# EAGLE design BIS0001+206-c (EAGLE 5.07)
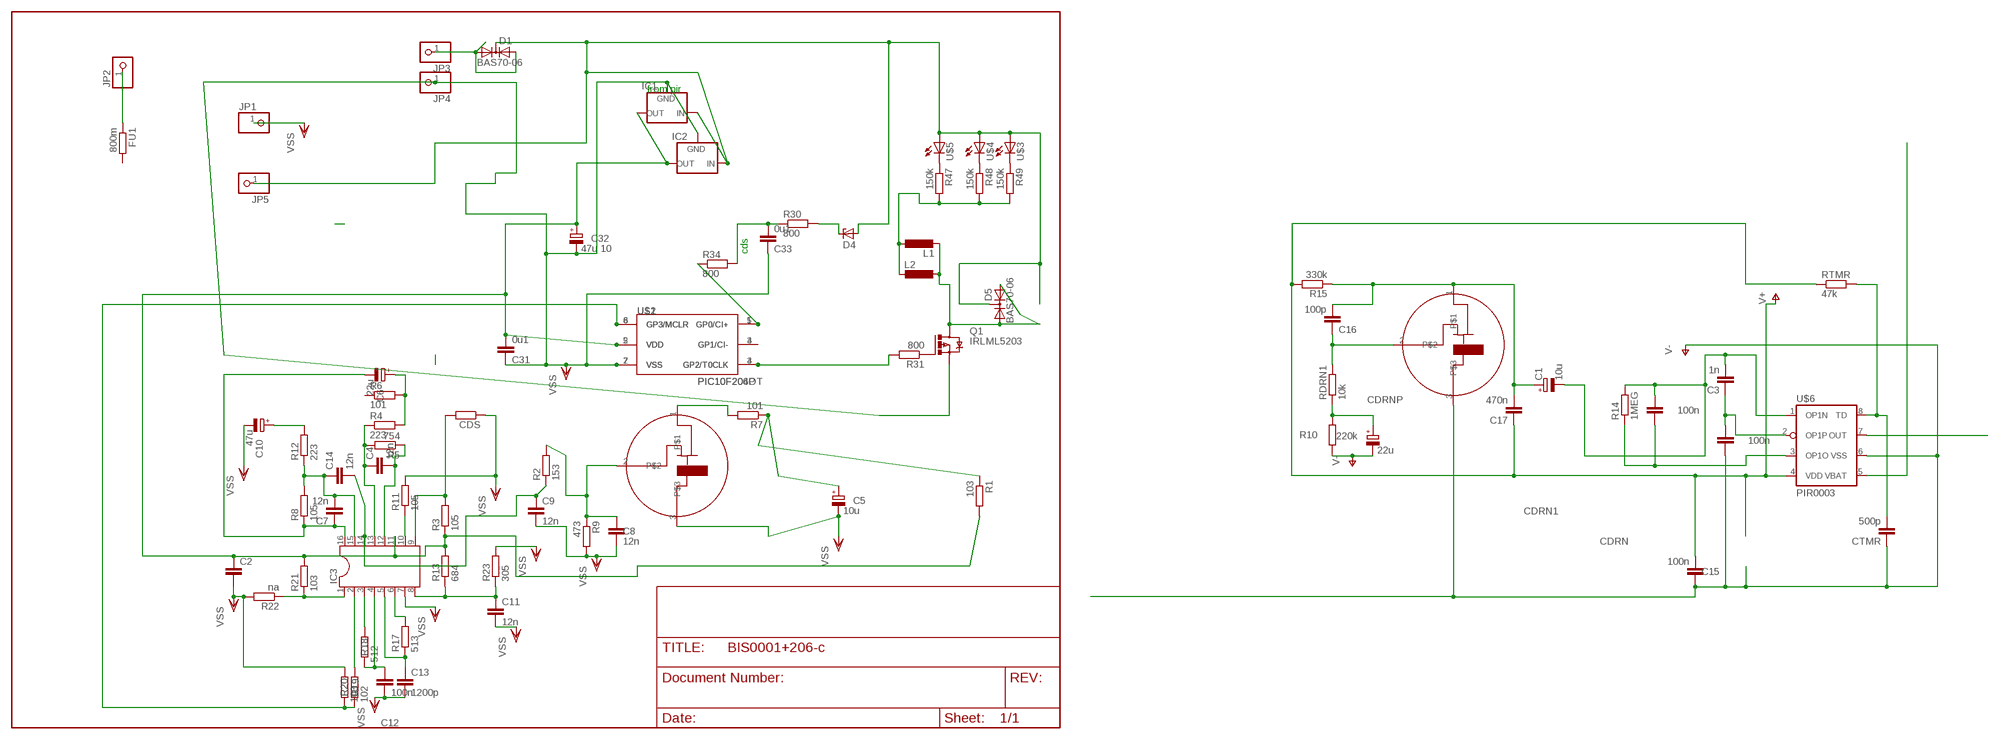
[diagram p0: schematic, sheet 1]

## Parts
C1  10u  CPOL-EUSMCA  [SMC_A]
C2  C-EUC0805  [C0805]
C3  1n  C-EUC0805  [C0805]
C4  12n  C-EUC0805  [C0805]
C5  10u  CPOL-EUE2.5-5  [E2,5-5]
C6  22u  CPOL-EUE2.5-5  [E2,5-5]
C7  12n  C-EUC0805  [C0805]
C8  12n  C-EUC0805  [C0805]
C9  12n  C-EUC0805  [C0805]
C10  47u  CPOL-EUE2.5-5  [E2,5-5]
C11  12n  C-EUC0805  [C0805]
C12  100n  C-EUC0805  [C0805]
C13  1200p  C-EUC0805  [C0805]
C14  12n  C-EUC0805  [C0805]
C15  100n  C-EUC1206  [C1206]
C16  100p  C-EUC0805  [C0805]
C17  470n  C-EUC0805  [C0805]
C31  0u1  C-EUC1206  [C1206]
C32  47u 10  CPOL-EUE2.5-5  [E2,5-5]
C33  0u1  C-EUC1206  [C1206]
CDRN  100n  C-EUC0805  [C0805]
CDRN1  100n  C-EUC0805  [C0805]
CDRNP  22u  CPOL-EUSMCB  [SMC_B]
CDS  R-EU_0207/5V  [0207/5V]
CTMR  500p  C-EUC0805  [C0805]
D1  BAS70-06  [SOT23]
D4  ZENER-DIODESOT23  [SOT23]
D5  BAS70-06  [SOT23]
FU1  800m  R-EU_0204/5  [0204/5]
IC1  XC63FPT  [TO92]
IC2  XC63FPP  [SOT89R]
IC3  DIL16SO16  [SO16]
JP1  PINHD-1X1  [1X01]
JP2  PINHD-1X1  [1X01]
JP3  PINHD-1X1  [1X01]
JP4  PINHD-1X1  [1X01]
JP5  PINHD-1X1  [1X01]
L1  L-EUL5650M  [L5650M]
L2  L-EU0207/7  [0207/7@1]
PIR  RE200B  [R200B]
PIR1  RE200B  [R200B]
Q1  IRLML5203  [MICRO3]
R1  103  R-EU_R0805  [R0805]
R2  153  R-EU_R0805  [R0805]
R3  105  R-EU_R0805  [R0805]
R4  223  R-EU_R0805  [R0805]
R5  754  R-EU_R0805  [R0805]
R6  101  R-EU_R0805  [R0805]
R7  101  R-EU_R0805  [R0805]
R8  105  R-EU_R0805  [R0805]
R9  473  R-EU_R0805  [R0805]
R10  220k  R-EU_R0805  [R0805]
R11  105  R-EU_R0805  [R0805]
R12  223  R-EU_R0805  [R0805]
R13  684  R-EU_R0805  [R0805]
R14  1MEG  R-EU_R0805  [R0805]
R15  330k  R-EU_R0805  [R0805]
R17  513  R-EU_R0805  [R0805]
R18  512  R-EU_R0805  [R0805]
R19  102  R-EU_R0805  [R0805]
R20  103  R-EU_R0805  [R0805]
R21  103  R-EU_R0805  [R0805]
R22  na  R-EU_R0805  [R0805]
R23  305  R-EU_R0805  [R0805]
R30  800  R-EU_R1206  [R1206]
R31  800  R-EU_R1206  [R1206]
R34  800  R-EU_R1206  [R1206]
R47  150k  R-EU_R1206  [R1206]
R48  150k  R-EU_R1206  [R1206]
R49  150k  R-EU_R1206  [R1206]
RDRN1  10k  R-EU_R0805  [R0805]
RTMR  47k  R-EU_R0805  [R0805]
U$1  PIC10F206P  [DIL8]
U$2  PIC10F204OT  [SOT23-6]
U$3  LED5MM  [LED5MM]
U$4  LED5MM  [LED5MM]
U$5  LED5MM  [LED5MM]
U$6  PIR0003  [SO08]

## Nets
GP3: U$6.7(OUT)
N$1: D1.1(A1) D1.2(A2) JP3.1
N$4: FU1.1 JP2.1
N$6: D4.3(C) R30.2
N$7: D1.3(C) D4.1(A) D5.3(C) IC1.2(IN) IC2.2(IN) JP5.1 U$3.A U$4.A U$5.A
N$8: C1.+ C16.2 C17.2 PIR1.1 R15.1
N$9: CDRNP.+ R10.2 RDRN1.1
N$10: Q1.1(G) R31.1
N$11: IC3.1 R21.1 R22.1
N$12: R19.1 R20.1 U$1.8(GP3/MCLR) U$2.6(GP3/MCLR)
N$13: U$1.4(GP1/CI-) U$2.3(GP1/CI-)
N$14: R31.2 U$1.3(GP2/T0CLK) U$2.4(GP2/T0CLK)
N$15: C1.- C3.2 CDRN1.2 R14.2 U$6.1(OP1N)
N$17: C33.2 R30.1 R34.2
N$18: C3.1 CDRN.2 U$6.2(OP1P)
N$20: CDRN1.1 R14.1 U$6.3(OP1O)
N$21: CTMR.2 RTMR.2 U$6.8(TD)
N$22: L1.1 L2.2 R47.2 R48.2 R49.2
N$23: C16.1 PIR1.2 RDRN1.2
N$24: IC3.2 R19.2
N$25: C12.1 IC3.4 R18.1
N$26: D5.1(A1) D5.2(A2) L1.2 L2.1 Q1.3(D)
N$27: IC3.3 R18.2
N$28: C11.1 IC3.8 R13.1 R23.1
N$29: R34.1 U$1.5(GP0/CI+) U$2.1(GP0/CI+)
N$30: C13.1 IC3.5 R17.1
N$31: IC3.6 R17.2
N$32: IC3.10 R11.1
N$34: C4.2 IC3.12 R5.1
N$35: C4.1 IC3.13 R4.1 R5.2
N$36: CDS.2 IC3.9 R3.2
N$37: C6.+ R4.2 R6.2
N$38: R47.1 U$5.K(C)
N$39: C9.1 C14.2 IC3.14 R2.1
N$40: C7.2 C14.1 IC3.15 R8.2 R12.1
N$41: C6.- C7.1 IC3.16 R8.1
N$42: PIR.1 R7.2
N$43: C5.+ R1.1 R7.1
N$44: C10.+ R12.2
N$46: C8.1 PIR.2 R2.2 R9.1
N$54: R48.1 U$4.K(C)
N$55: R49.1 U$3.K(C)
V2CC: C2.1 C31.2 C32.+ IC1.3(OUT) IC2.3(OUT) IC3.11 R1.2 R3.1 R13.2 R21.2 U$1.2(VDD) U$2.5(VDD)
V5: U$6.5(VBAT)
V+: C15.2 C17.1 R15.2 RTMR.1 U$6.4(VDD)
V-: C15.1 CDRN.1 CDRNP.- CTMR.1 PIR1.3 R10.1 U$6.6(VSS)
VSS: C2.2 C5.- C8.2 C9.2 C10.- C11.2 C12.2 C13.2 C31.1 C32.- C33.1 CDS.1 IC1.1(GND) IC2.1(GND) IC3.7 JP1.1 JP4.1 PIR.3 Q1.2(S) R9.2 R11.2 R20.2 R22.2 R23.2 U$1.7(VSS) U$2.2(VSS)
Unconnected: FU1.2 R6.1

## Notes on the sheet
- from pir
- cds

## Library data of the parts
C1 C5 C6 C10 C32 CDRNP = rcl:CPOL-EU: POLARIZED CAPACITOR, European symbol
C2 C4 C7-C9 C11-C14 = rcl-2:C-EU: CAPACITOR, European symbol
C3 C15-C17 C31 C33 CDRN CDRN1 CTMR = rcl:C-EU: CAPACITOR, European symbol
CDS = rcl(2):R-EU_: RESISTOR, European symbol
D1 D5 = diode-1:BAS70-06: Silicon Schottky Diodes General-purpose diode for high-speed switching
D4 = diode-1:ZENER-DIODE: Z-Diode
FU1 R10 R14 R15 R30 R31 R34 R47-R49 RDRN1 RTMR = rcl:R-EU_: RESISTOR, European symbol
IC1 IC2 = v-reg:XC63FP: Positiv Voltage Regulators www.torex.co.jp/english/product/pro02/pdf/0201_xc62fp.pdf
IC3 = ic-package:DIL16: Dual In Line / Socket
JP1-JP5 = pinhead:PINHD-1X1: PIN HEADER
L1 = rcl-2:L-EU: INDUCTOR, European symbol
L2 = rcl:L-EU: INDUCTOR, European symbol
PIR PIR1 = photo-elements:RE200B
Q1 = transistor-power:IRLML5203: HEXFET P-Channel Power MOSFET
R1-R9 R11-R13 R17-R23 = rcl-2:R-EU_: RESISTOR, European symbol
U$1 U$2 = microchip-3:PIC10F2*: uPC nW 0,25/0,5k Program Flash memory Comparator
U$3-U$5 = led(3):LED: LED
U$6 = linear:PIR0003

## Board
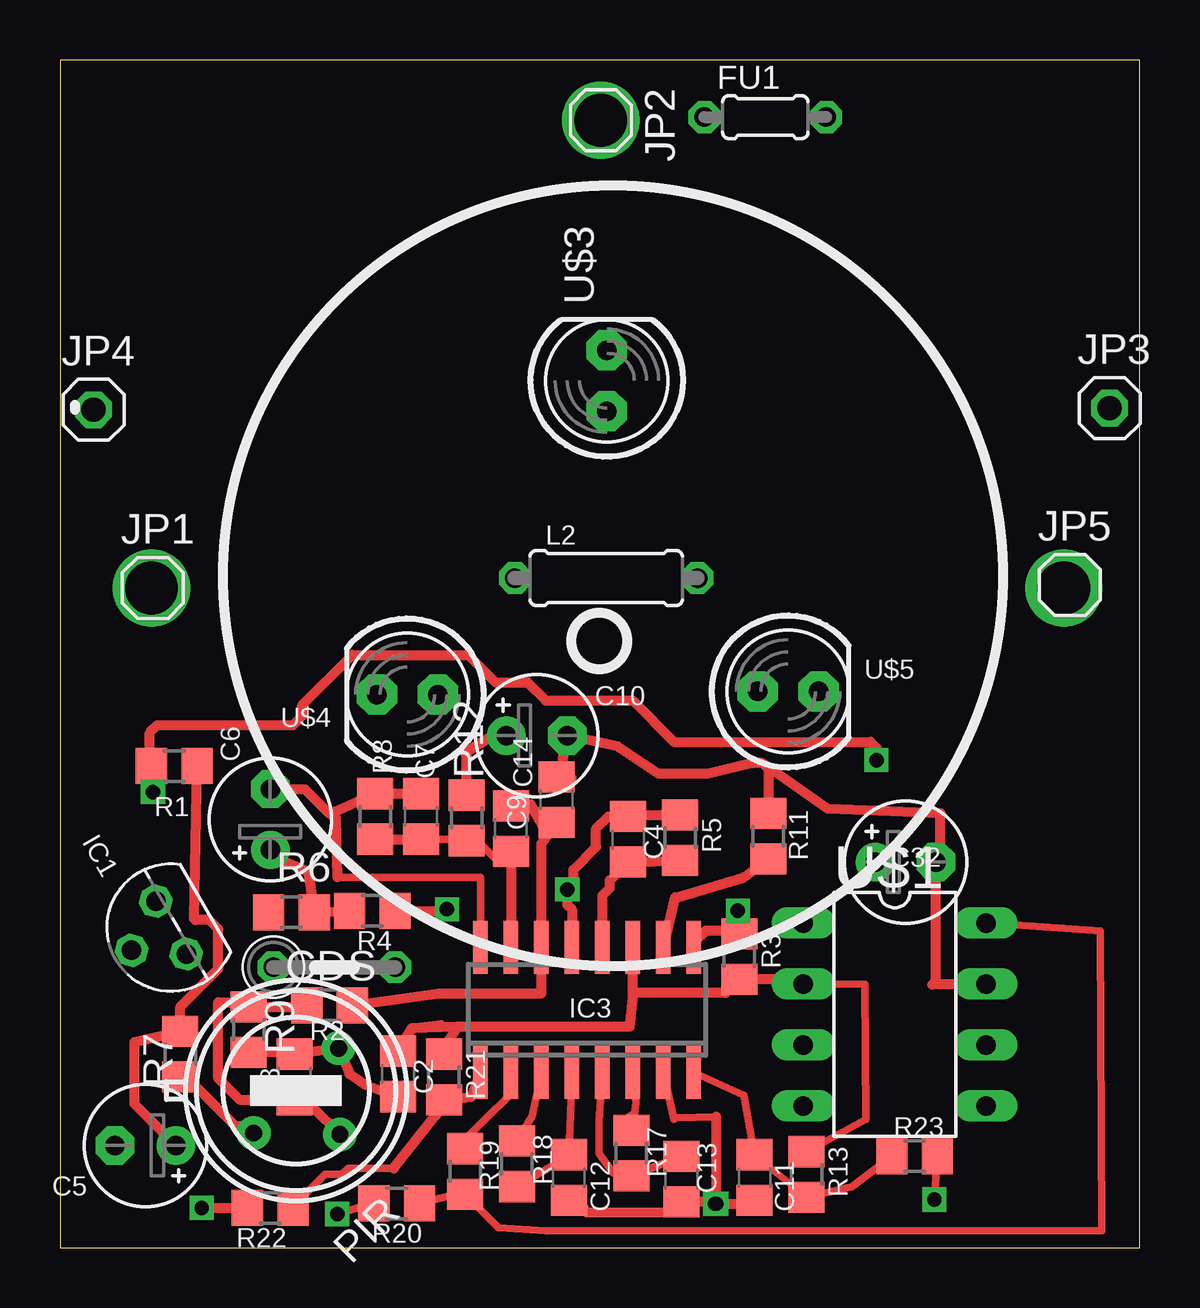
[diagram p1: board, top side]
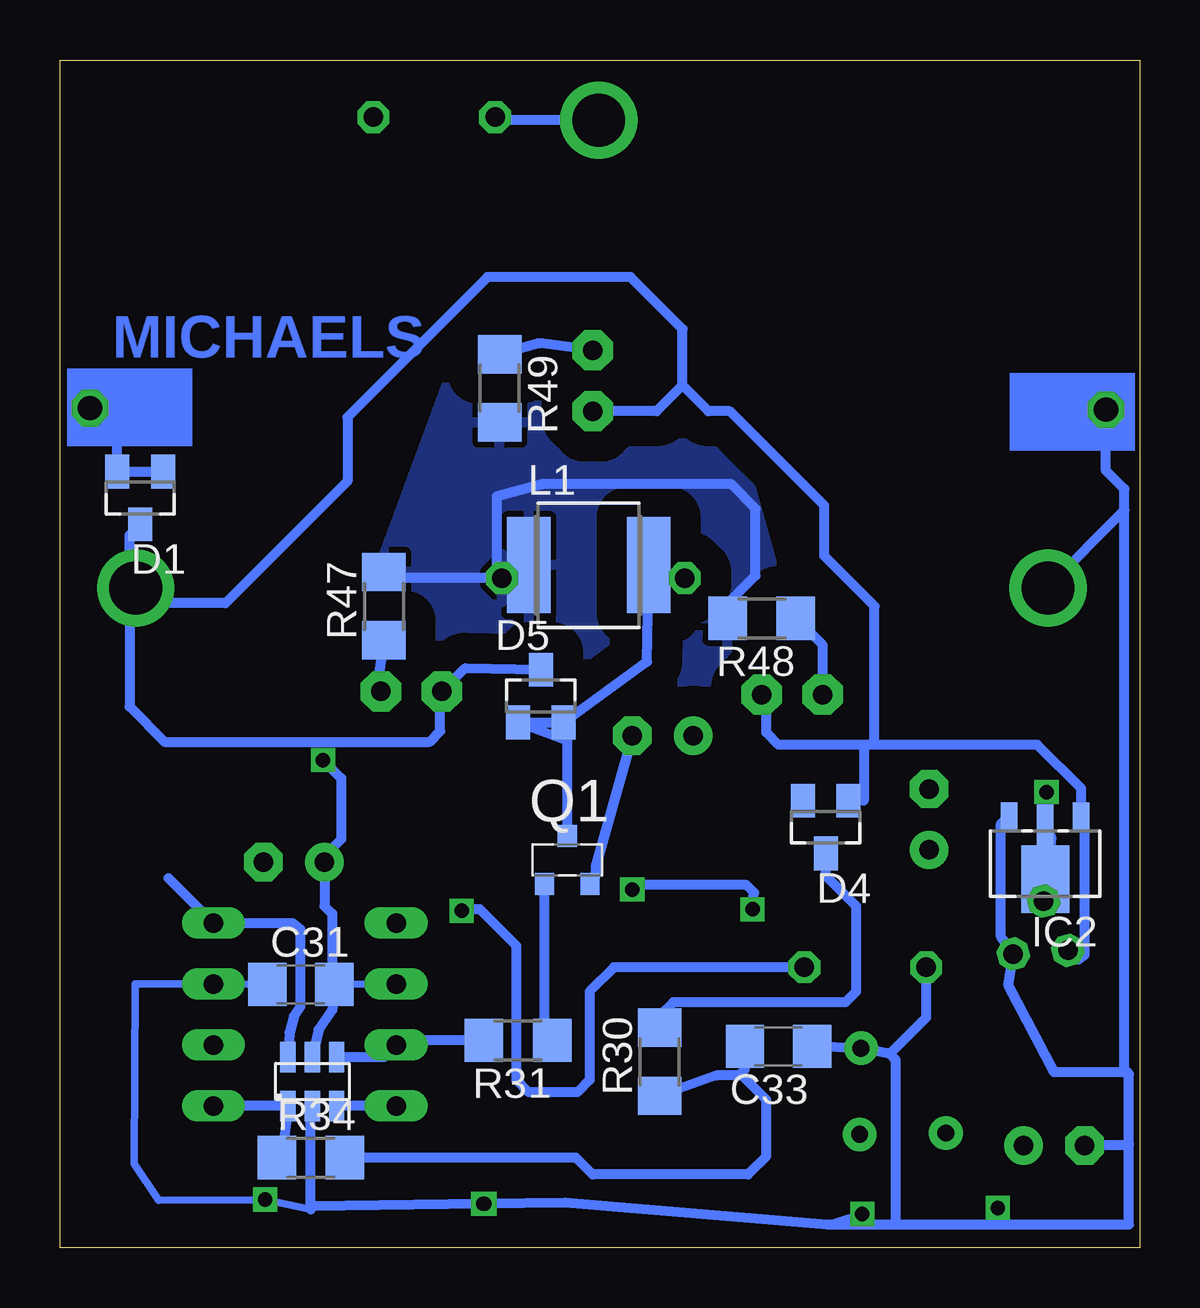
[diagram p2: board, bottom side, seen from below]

Size 45 x 49.5 mm. Coordinates in mm from the lower left corner, seen from the top.
Outline: 0,0 45,0 45,49.5 0,49.5 0,0
Copper layers (1*16): Top 0.035mm / dielectric 1.5mm / Bottom 0.035mm
Design rules "default": minimum track width 10mil, minimum drill 24mil, track to track 8mil, track to pad 8mil, pad to pad 8mil, via to via 8mil, smd to smd 8mil, copper to edge 40mil, drill to drill 8mil, minimum pad ring 10mil, minimum via ring 8mil, stop-mask expansion 4mil, vias tented up to drill 0mil, thermal gap 10mil

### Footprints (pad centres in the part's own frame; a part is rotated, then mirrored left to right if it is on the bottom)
SMC_A = smd 1.6 x 1.4: + -1.5,0; - 1.5,0
C0805 = smd 1.3 x 1.5: 1 -0.95,0; 2 0.95,0
E2,5-5 = drill 0.813 pad 1.6 round: + -1.27,0 | drill 0.813 pad 1.6 octagon: - 1.27,0
C1206 = smd 1.6 x 1.8: 1 -1.4,0; 2 1.4,0
SMC_B = smd 1.6 x 2.4: + -1.5,0; - 1.5,0
0207/5V = drill 0.813 octagon: 1 -2.54,0; 2 2.54,0
SOT23 = smd 1 x 1.4: 1 -0.95,-1.1; 2 0.95,-1.1; 3 0,1.1
0204/5 = drill 0.813 octagon: 1 -2.54,0; 2 2.54,0
TO92 = drill 0.813 octagon: 1 -1.27,0; 2 0,1.905; 3 1.27,0
SOT89R = smd 0.7 x 1.1: 1 1.5,-1.75; 2 -1.5,-1.75 | smd 0.7 x 1.8: 3 0,-1.4 | smd 2 x 2.8: 4 0,0.9
SO16 = smd 0.6 x 2.2: 1 -4.445,-2.6; 2 -3.175,-2.6; 3 -1.905,-2.6; 4 -0.635,-2.6; 5 0.635,-2.6; 6 1.905,-2.6; 7 3.175,-2.6; 8 4.445,-2.6; 9 4.445,2.6; 10 3.175,2.6; 11 1.905,2.6; 12 0.635,2.6; 13 -0.635,2.6; 14 -1.905,2.6; 15 -3.175,2.6; 16 -4.445,2.6
1X01 = drill 1.016 octagon: 1 0,0
L5650M = smd 1.8 x 4: 1 -2.5,0; 2 2.5,0
0207/7@1 = drill 0.813 octagon: 1 -3.81,0; 2 3.81,0
R200B = drill 0.7 pad 1.4 round: 1 -2.5,0; 2 0,-2.58; 3 2.5,0
MICRO3 = smd 0.8 x 0.9: 1 -0.95,-1; 2 0.95,-1; 3 0,1
R0805 = smd 1.3 x 1.5: 1 -0.95,0; 2 0.95,0
R1206 = smd 1.6 x 1.803: 1 -1.422,0; 2 1.422,0
DIL8 = drill 0.813 long: 1 -3.81,-3.81; 2 -1.27,-3.81; 3 1.27,-3.81; 4 3.81,-3.81; 5 3.81,3.81; 6 1.27,3.81; 7 -1.27,3.81; 8 -3.81,3.81
SOT23-6 = smd 0.635 x 1.27: 1 -1.016,-1.016; 2 0,-1.016; 3 1.016,-1.016; 4 1.016,1.016; 5 0,1.016; 6 -1.016,1.016
LED5MM = drill 0.813 pad 1.676 octagon: A -1.27,0; K 1.27,0
SO08 = smd 0.6 x 2.2: 1 -1.905,-2.6; 2 -0.635,-2.6; 3 0.635,-2.6; 4 1.905,-2.6; 5 1.905,2.6; 6 0.635,2.6; 7 -0.635,2.6; 8 -1.905,2.6

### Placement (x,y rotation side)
C1  not placed on the board
C2  14.1,7.24 270 top
C3  not placed on the board
C4  23.69,17.02 270 top
C5  3.56,4.25 180 top
C6  8.76,17.84 90 top
C7  15.05,17.97 270 top
C8  9.78,7.11 90 top
C9  20.7,18.67 90 top
C10  19.88,21.34 0 top
C11  28.96,2.92 270 top
C12  21.21,2.92 270 top
C13  25.91,2.86 270 top
C14  18.8,17.46 90 top
C15  not placed on the board
C16  not placed on the board
C17  not placed on the board
C31  34.96,10.96 0 bottom
C32  35.24,16.07 0 top
C33  15.05,8.38 180 bottom
CDRN  not placed on the board
CDRN1  not placed on the board
CDRNP  not placed on the board
CDS  11.43,11.68 0 top
CTMR  not placed on the board
D1  41.66,31.24 180 bottom
D4  13.08,17.53 180 bottom
D5  24.96,22.99 0 bottom
FU1  29.4,47.12 0 top
IC1  4.63,13.34 120 top
IC2  3.94,16.26 180 bottom
IC3  21.97,9.91 0 top
JP1  3.87,27.5 0 top
JP2  22.54,46.99 270 top
JP3  43.75,34.99 0 top
JP4  1.4,34.92 0 top
JP5  42.1,27.62 0 top
L1  22.96,28.44 0 bottom
L2  22.77,27.91 0 top
PIR  9.84,6.54 45 top
PIR1  not placed on the board
Q1  23.85,16.16 0 bottom
R1  4.76,20.07 180 top
R2  11.24,10.1 180 top
R3  28.32,12.13 90 top
R4  13.02,14.03 180 top
R5  25.84,17.08 90 top
R6  9.65,13.97 0 top
R7  5.02,8.06 270 top
R8  13.14,17.97 270 top
R9  7.87,9.08 270 top
R10  not placed on the board
R11  29.53,17.14 90 top
R12  16.95,17.91 90 top
R13  31.11,3.05 90 top
R14  not placed on the board
R15  not placed on the board
R17  23.81,3.94 90 top
R18  19.05,3.49 90 top
R19  16.89,3.17 90 top
R20  14.03,1.84 180 top
R21  16,7.11 90 top
R22  8.76,1.65 180 top
R23  35.62,3.81 0 top
R30  20,7.75 90 bottom
R31  25.91,8.64 180 bottom
R34  34.54,3.75 0 bottom
R47  31.5,26.73 90 bottom
R48  15.75,26.23 180 bottom
R49  26.67,35.81 270 bottom
RDRN1  not placed on the board
RTMR  not placed on the board
U$1  34.8,9.72 270 top
U$2  34.48,6.92 0 bottom
U$3  22.8,36.13 90 top
U$4  14.48,23.05 180 top
U$5  30.35,23.18 0 top
U$6  not placed on the board

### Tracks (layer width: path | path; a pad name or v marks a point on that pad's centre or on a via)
N$1
  Bottom 0.406: JP3.1 42.61,33.84 D1.2 D1.1
N$2  (via drill 2.2)
  other vias: 3.81,27.5
N$3  (via drill 2.2)
  other vias: 41.85,27.5
N$4
  Bottom 0.406: JP2.1 26.73,46.99 FU1.1
N$5  (via drill 2.2)
  other vias: 22.54,46.99
N$6
  Bottom 0.406: R30.2 20,9.65 19.43,10.22 12.26,10.22 11.81,10.67 11.81,14.22 13.08,15.49 D4.3
N$7
  Bottom 0.406: D5.3 28.11,24.15 U$5.A 29.15,23.11 29.15,21.53 29.59,21.08 40.64,21.08 42.1,22.54 JP5.1 | IC1.2 2.54,12.01 2.29,12.19 2.29,17.6 IC2.2 2.44,19.14 4.25,20.95 10.99,20.95 | 10.99,20.95 11.49,20.95 | 11.49,20.95 15.05,20.95 15.56,21.46 15.56,22.86 U$4.A | 10.99,20.95 11.05,21.02 11.05,26.73 13.14,28.83 13.14,30.92 17.08,34.86 17.97,34.86 19.05,35.94 | JP5.1 42.1,29.7 D1.3 | U$3.A 20.13,34.86 19.05,35.94 | 19.05,35.94 19.05,38.29 21.21,40.45 27.18,40.45 33.02,34.61 33.02,31.94 38.1,26.86 41.34,26.86 JP5.1 | D4.1 11.49,18.63 11.49,20.95
N$8  (4 unrouted)
N$9  (2 unrouted)
N$10
  Bottom 0.406: R31.1 24.8,8.64 Q1.1
N$11
  Top 0.305: 9.71,1.71 11.05,3.05 11.75,3.05 12,3.3 13.91,3.3
  Top 0.406: IC3.1 17.15,6.29 R21.1 15.68,5.84 15.68,5.52 13.91,3.3 | R22.1 9.71,1.71
N$12
  Top 0.305: R20.1 16.76,2.29 R19.1 18.29,0.83 20.26,0.7 43.43,0.7 43.37,13.21 U$1.8
  Bottom 0.406: U$1.8 35.31,13.53 34.99,13.27 34.99,10.03 35.24,9.65 35.43,8.95 U$2.6 | U$1.8 39.47,13.14 | U$1.8 40.47,15.39
N$13
  Bottom 0.406: U$1.4 U$2.3
N$14
  Bottom 0.406: U$2.4 31.5,7.94 U$1.3 30.99,8.64 R31.2 27.27,8.06
N$15  (4 unrouted)
N$17
  Bottom 0.406: R34.2 23.5,3.75 22.8,3.05 16.32,3.05 15.56,3.81 15.56,6.16 16.57,7.18 16.7,7.18 | 16.7,7.18 17.63,7.18 R30.1 | C33.2 16.45,7.43 16.7,7.18
N$18  (2 unrouted)
N$20  (2 unrouted)
N$21  (2 unrouted)
N$22
  Bottom 0.406: L2.2 31.25,27.91 R47.2 | R48.2 17.17,26.84 16,28 16,30.8 17.02,31.81 24.89,31.81 26.8,31.3 26.8,28.13 L2.2 | L1.1 26.23,28.25 L2.2
  pour Bottom (isolate 1.27, rank 2): 21.97,38.29 28.07,38.23 35.81,17.21 12.19,17.4 17.97,37.97 21.59,38.23
N$23  (2 unrouted)
N$24
  Top 0.305: IC3.2 18.67,6.29 17.78,5.4 17.02,4.63 R19.2
N$25
  Top 0.305: IC3.4 C12.1 20.45,3.37 R18.1
N$26
  Bottom 0.406: Q1.3 23.85,21.1 D5.1 D5.2 20.52,24.42 L1.2 20.18,27.91 L2.1
N$27
  Top 0.305: IC3.3 19.68,5.46 R18.2
N$28
  Top 0.305: IC3.8 28.51,6.35 C11.1 R13.1 33.02,2.54 R23.1
N$29
  Bottom 0.406: U$1.5 U$2.1 35.75,3.71 R34.1
N$30
  Top 0.305: IC3.5 22.48,5.27 22.48,3.94 23.05,3.11 R17.1 C13.1
N$31
  Top 0.305: IC3.6 24,6.03 23.94,5.59 23.43,5.27 R17.2
N$32
  Top 0.406: IC3.10 25.65,14.61 25.78,14.61 28.51,15.43 R11.1
N$34
  Top 0.406: IC3.12 22.61,14.67 22.92,14.99 22.92,15.31 C4.2 24.32,16.07 R5.1
N$35  (via drill 0.6)
  Top 0.406: R4.1 15.88,14.03 v16.13,14.1 | IC3.13 21.34,14.1 21.14,14.29 v21.14,14.92 21.4,15.18 21.4,15.75 22.35,16.7 22.35,17.46 22.86,17.97 23.18,17.97 | 23.18,17.97 C4.1 | R5.2 23.24,18.03 23.18,17.97
  Bottom 0.406: v16.13,14.1 16.07,14.8 16.38,15.11 20.95,15.11 v21.14,14.92
N$36  (via drill 0.6)
  Top 0.406: IC3.9 26.42,12.7 26.92,13.21 28.19,13.21 R3.2 28.26,13.14 v28.26,14.03
  Bottom 0.406: CDS.2 21.91,11.68 22.92,10.67 22.92,6.99 23.43,6.48 25.46,6.48 25.97,6.99 25.97,12.57 27.5,14.1 28.19,14.1 v28.26,14.03
N$37
  Top 0.406: R4.2 R6.2 10.35,15.68 9.02,16.26 9.21,16.45 C6.+
N$38
  Bottom 0.406: U$5.K 31.81,23.18 R47.1
N$39
  Top 0.406: R2.1 15.78,10.59 20.07,10.59 IC3.14 20.07,16.83 C9.1 20.13,17.59 19.62,18.48 19.12,18.16 C14.2
N$40
  Top 0.305: C7.2 16.89,17.02 R12.1 17.4,16.96 18.16,16.19 18.48,16.19 C14.1
  Top 0.406: R8.2 C7.2 | C14.1 IC3.15
N$41
  Top 0.305: IC3.16 17.53,15.43 11.56,15.43
  Top 0.406: 11.56,15.43 11.49,17.91 11.21,18.11 | 11.21,18.11 11.43,18.16 R8.1 C7.1 | C6.- 10.21,19.11 11.21,18.11
N$42
  Top 0.406: R7.2 5.27,7.11 7.3,5.08 7.77,5.08 PIR.1
N$43
  Top 0.406: R1.1 5.59,13.72 5.65,13.65 6.22,13.65 6.6,13.27 6.6,11.62 5.02,10.03 R7.1 3.11,8.57 3.11,5.97 C5.+
N$44
  Top 0.406: C10.+ 18.03,21.34 16.89,20.64 16.95,20.51 R12.2
N$46
  Top 0.406: R2.2 10.22,10.03 R9.1 7.68,10.22 6.6,10.22 6.6,7.05 7.49,6.16 C8.1 10.49,6.16 10.49,5.89 PIR.2
N$54
  Bottom 0.406: 13.27,22.99 U$4.K 13.21,25.11 R48.1
N$55
  Bottom 0.406: U$3.K 25.02,37.69 R49.1
V2CC  (via drill 0.6)
  Top 0.305: R13.2 33.59,5.33 C31.2 U$1.2
  Top 0.406: 23.88,10.6 IC3.11 | 23.88,10.6 23.75,9.21 16.57,9.21 | 16.57,9.21 14.67,9.14 | 14.67,9.14 C2.1 | R21.2 16.19,8.64 16.57,9.21 | 23.88,10.6 27.75,10.6 R3.1 30.8,11.18 U$1.2 | 14.67,9.14 15.88,9.27 | v3.87,18.99 3.87,20 R1.2 3.75,20.13 3.75,21.46 4.06,21.78 9.72,21.78 10.1,22.16 10.1,22.61 12.19,24.7 17.02,24.7 18.16,23.56 19.49,23.56 20.26,22.8 23.88,22.8 25.59,21.08 33.78,21.08 34.04,20.83 v34.04,20.32
  Bottom 0.305: C31.2 U$1.2
  Bottom 0.406: U$2.5 34.23,9.08 33.66,9.91 33.59,10.36 C31.2 33.66,11.06 33.66,13.91 33.97,14.22 C32.+ 33.97,16.32 33.27,17.02 33.27,19.56 v34.04,20.32 | IC1.3 3.67,17.07 IC2.3 3.94,18.92 v3.87,18.99
V+  (4 unrouted)
V-  (6 unrouted)
VSS  (via drill 0.6)
  Top 0.305: v11.56,1.4 R20.2 | C13.2 26.01,1.9 | IC3.7 25.59,5.33 25.65,5.4 27.36,5.45 | v36.45,2 R23.2
  Top 0.406: C2.2 12.7,6.8 12.06,7.24 PIR.3 C8.2 9.71,8.13 R9.2 | v5.91,1.65 R22.2 | C10.- 23.24,20.89 24.96,19.75 26.99,19.75 28.89,20.19 29.27,20.19 | C9.2 21.34,19.56 20.95,19.94 20.95,20.38 C10.- | U$1.7 38.59,10.96 C31.1 36.51,11.12 C32.- 36.7,16.26 36.7,18.1 32,18.29 29.27,20.19 | R11.2 29.53,19.94 29.27,20.19 | C10.- 21.21,21.27 | v27.3,1.82 27.22,1.91 C13.2 25.71,1.45 21.96,1.45 21.69,1.97 C12.2 | 27.36,5.45 v27.36,1.82 28.81,1.82 C11.2
  Bottom 0.305: 13.02,0.95 v11.56,1.4 | 34.54,1.59 v36.45,2 40.89,1.97 41.91,3.49 41.86,11 U$1.7 C31.1
  Bottom 0.406: U$2.2 34.54,5.91 34.54,1.71 | 34.54,1.71 34.54,1.59 | 5.91,0.95 0.45,0.95 0.45,4.32 | 5.91,0.95 10.16,0.95 | 10.16,0.95 13.02,0.95 23.94,1.87 v27.3,1.82 | v27.3,1.82 v27.36,1.82 | v27.36,1.82 34.54,1.71 | 0.45,4.32 0.45,7.24 0.51,7.3 | IC2.1 5.78,17.66 5.78,12.95 5.46,12.57 IC1.1 5.46,10.92 3.56,7.3 0.51,7.3 | C5.- 0.51,4.25 0.45,4.32 | 5.91,0.95 v5.91,1.65 | Q1.2 22.67,15.5 22.67,15.87 C10.- | v27.3,1.82 v27.36,1.82 | JP4.1 1.4,32.38 0.64,31.62 0.64,30.73 | 0.64,30.73 0.64,7.43 0.51,7.3 | 0.64,30.73 JP1.1 | CDS.1 8.89,9.59 10.41,8.06 | 10.16,0.95 10.16,7.81 10.41,8.06 | 10.41,8.06 PIR.3 C33.1
(copper drawn outside any net)
  shapes: Bottom area x2

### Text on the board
Bottom: MICHAELS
